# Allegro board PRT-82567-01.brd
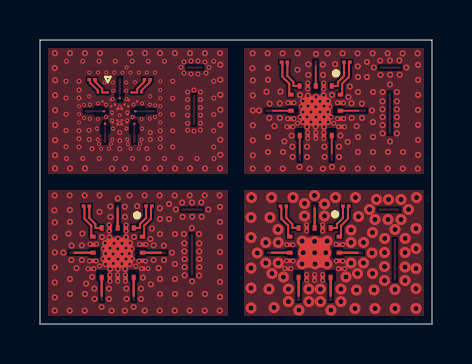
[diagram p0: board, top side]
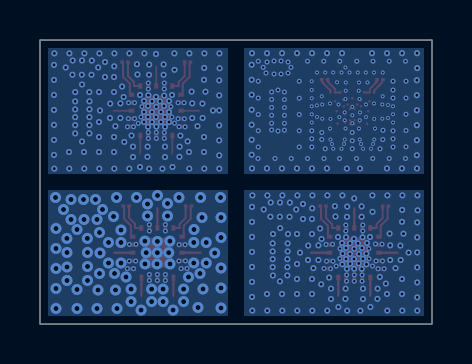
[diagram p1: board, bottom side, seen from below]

Outline 19.6 x 14.2 mm; copper layers: TOP, LAYER_2, LAYER_3, BOTTOM. Coordinates in mm from the lower left corner of the outline.
Outline path: 0,14.2 0,0 19.6,0 19.6,14.2 0,14.2

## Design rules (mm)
constraint set DEFAULT: min track width 0.1
nets with their own width: min track width 0.075; nets RF1_4 RF2_4 RF3_4 RF4_4 RFC_4

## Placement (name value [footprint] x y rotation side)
NOREF  -  []  9.8 14.51 0 top
NOREF#2  -  []  19.6 0 90 top
NOREF#3  -  []  59.4 56.6 0 top
NOREF#4  -  []  -14.29 -36.18 0 top
NOREF#5  -  []  0 0 0 top
NOREF#6  -  []  -35.6 51.6 0 top
NOREF#7  -  []  -27.01 -52.55 0 top
NOREF#8  -  []  -200.87 86.32 0 top
NOREF#9  -  []  70.93 -66.91 0 top
NOREF#10  -  []  -0.19 7.09 0 top
U1  -  [IC_LGA_3P0X3P0_21P]  3.88 3.56 270 top
U2  -  [IC_LGA_3P0X3P0_21P]  13.73 3.56 270 top
U3  -  [IC_DIE_2440X2094_33]  3.98 10.66 0 top
U4  -  [IC_LGA_3P0X3P0_21P]  13.78 10.66 270 top

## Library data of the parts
U1 U2 U4 = IC_SHAGGY_LGA_21P
U3 = IC_SHAGGY_DIE_33P

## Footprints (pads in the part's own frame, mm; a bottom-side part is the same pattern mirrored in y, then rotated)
IC_DIE_2440X2094_33
  round 0.127 smd: 1(1.091,0.913) 2(0.592,0.913) 3(-0.592,0.913) 4(-1.091,0.913) 5(-1.129,-0.959) 6(-0.303,-0.94) 7(0.303,-0.94) 8(1.129,-0.959) 9(1.091,-0.412) 10(0.859,0.47) 11(0.785,-0.027) 12(0.732,-0.648) 13(0.428,0.216) 14(0.446,0.531) 15(0.353,-0.585) 16(0.379,-0.181) 17(0.239,0.306) 18(0.114,-0.68) 19(0.114,-0.48) 20(0.114,0.091) 21(0,0.629) 22(-0.114,-0.68) 23(-0.114,-0.48) 24(-0.114,0.091) 25(-0.239,0.306) 26(-0.353,-0.585) 27(-0.379,-0.181) 28(-0.428,0.216) 29(-0.446,0.531) 30(-0.732,-0.648) 31(-0.785,-0.027) 32(-0.859,0.47) 33(-1.091,-0.412)
IC_LGA_3P0X3P0_21P
  rect 0.275x0.2 smd: 1(-1.238,0.8) 2(-1.238,0.4) 3(-1.238,0) 4(-1.238,-0.4) 5(-1.238,-0.8) 11(1.238,-0.8) 12(1.238,-0.4) 13(1.238,0) 14(1.238,0.4) 15(1.238,0.8)
  rect 0.2x0.275 smd: 6(-0.8,-1.238) 7(-0.4,-1.238) 8(0,-1.238) 9(0.4,-1.238) 10(0.8,-1.238) 16(0.8,1.238) 17(0.4,1.238) 18(0,1.238) 19(-0.4,1.238) 20(-0.8,1.238)
  rrect 1.5x1.5 smd: 21(0,0)

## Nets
GND_1: U1.2 U1.4 U1.7 U1.9 U1.10 U1.12 U1.13 U1.14 U1.16 U1.17 U1.19 U1.21
GND_2: U2.2 U2.4 U2.7 U2.9 U2.10 U2.12 U2.13 U2.14 U2.16 U2.17 U2.19 U2.21
GND_3: U3.5 U3.6 U3.7 U3.8 U3.9 U3.10 U3.13 U3.14 U3.15 U3.16 U3.17 U3.18 U3.19 U3.20 U3.22 U3.23 U3.24 U3.25 U3.26 U3.27 U3.28 U3.29 U3.32 U3.33
GND_4: U4.2 U4.4 U4.7 U4.9 U4.10 U4.12 U4.13 U4.14 U4.16 U4.17 U4.19 U4.21
V1_1: U1.1
V1_2: U2.1
V1_3: U3.2
V1_4: U4.1
V2_1: U1.20
V2_2: U2.20
V2_3: U3.1
V2_4: U4.20
VDD_1: U1.6
VDD_2: U2.6
VDD_3: U3.4
VDD_4: U4.6
VSS_1: U1.5(VSS_EXT)
VSS_2: U2.5(VSS_EXT)
VSS_3: U3.3(VSS_EXT)
VSS_4: U4.5(VSS_EXT)
RF1_1: U1.18
RF1_2: U2.18
RF1_3: U3.11
RF1_4: U4.18
RF2_1: U1.15
RF2_2: U2.15
RF2_3: U3.12
RF2_4: U4.15
RF3_1: U1.11
RF3_2: U2.11
RF3_3: U3.30
RF3_4: U4.11
RF4_1: U1.8
RF4_2: U2.8
RF4_3: U3.31
RF4_4: U4.8
RFC_1: U1.3
RFC_2: U2.3
RFC_3: U3.21
RFC_4: U4.3

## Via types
v1: diameter 0.304, hole 0.152, TOP to BOTTOM, 316 vias
v2: diameter 0.25, hole 0.127, TOP to BOTTOM, 153 vias
v3: diameter 0.2, hole 0.102, TOP to BOTTOM, 68 vias
v4: diameter 0.55, hole 0.25, TOP to BOTTOM, 85 vias

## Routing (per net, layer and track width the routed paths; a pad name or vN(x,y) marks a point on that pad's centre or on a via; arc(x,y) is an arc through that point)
GND_1: length 0.9
  TOP w0.1: v2(4.97,3.98) 5.1,3.98 U1.19 ; v2(3.46,4.95) 3.46,4.83 U1.4 3.46,4.78 v2(3.46,4.65) ; v2(4.95,3.14) 5.1,3.14 U1.17 ; U1.16 v2(5.08,2.76) ; U1.9 2.66,3.15 v2(2.8,3.15)
  vias: v1(0.73,6.43) v1(0.72,5.68) v1(0.74,5.08) v1(0.74,4.33) v1(0.74,3.58) v1(0.74,2.83) v1(0.74,2.08) v1(0.74,1.33) v1(0.73,0.67) v1(1.17,3.57) v1(1.43,4.51) v1(1.48,6.43) v1(1.49,5.71) v1(1.5,5.11) v1(1.5,2.25) v1(1.5,1.5) v1(1.49,0.67) v1(1.58,3.92) v1(1.57,3.2) v1(1.82,2.79) v1(2.12,4.52) v1(2.09,3.93) v1(2.09,3.2) v1(2.23,6.43) v1(2.25,1.5) v1(2.23,0.67) v1(2.31,2.02) v1(2.61,2.35) v1(2.72,1.77) v1(2.73,1.26) v1(2.98,6.43) v1(2.98,5.61) v1(3.1,4.35) v1(3.08,0.85) v1(3.25,4.05) v1(3.28,3.52) v1(3.28,2.98) v1(3.45,1.77) v1(3.45,1.25) v1(3.52,5.88) v1(3.52,5.36) v1(3.47,4.33) v1(3.5,3.8) v1(3.45,3.26) v1(3.51,2.76) v1(3.65,3.5) v1(3.58,0.67) v1(3.7,4.03) v1(3.67,3.03) v1(3.89,6.28) v1(3.9,4.26) v1(3.88,3.76) v1(3.9,3.25) v1(3.89,2.76) v1(4.1,4.03) v1(4.1,3.5) v1(4.09,3.02) v1(4.24,5.87) v1(4.25,5.36) v1(4.24,0.67) v1(4.3,4.34) v1(4.3,3.8) v1(4.3,3.25) v1(4.26,2.76) v1(4.32,1.77) v1(4.33,1.26) v1(4.48,6.43) v1(4.5,4.05) v1(4.46,3.52) v1(4.49,2.98) v1(4.7,4.35) v1(4.68,0.85) v1(4.83,5.38) v1(4.86,5.89) v1(5.05,1.77) v1(5.05,1.25) v1(5.14,2.32) v1(5.23,6.43) v1(5.24,0.67) v1(5.52,4.25) v1(5.54,1.98) v1(5.59,4.78) v1(5.68,3.93) v1(5.68,3.2) v1(5.93,2.79) v1(5.98,6.43) v1(5.99,5.79) v1(6,5.25) v1(6,4.5) v1(6,2.25) v1(6,1.5) v1(5.99,0.67) v1(6.19,3.92) v1(6.2,3.2) v1(6.45,6) v1(6.45,5.25) v1(6.6,3.57) v1(6.73,6.43) v1(6.74,0.67) v1(6.79,5.72) v1(6.75,4.5) v1(6.75,3) v1(6.75,2.25) v1(6.75,1.5) v1(7.11,6.07) v1(7.12,5.36) v1(7.2,4.5) v1(7.22,4.03) v1(7.22,3.63) v1(7.23,3.24) v1(7.23,2.84) v1(7.23,2.43) v1(7.48,6.43) v1(7.5,1.5) v1(7.49,0.67) v1(7.6,6.08) v1(7.61,5.37) v1(7.59,4.79) v1(7.6,2.13) v1(7.95,4.5) v1(7.97,4.03) v1(7.97,3.63) v1(7.97,3.24) v1(7.97,2.84) v1(7.96,2.42) v1(8.06,6.08) v1(8.08,5.37) v1(8.23,6.43) v1(8.25,1.5) v1(8.23,0.67) v1(8.41,5.72) v1(8.98,6.43) v1(9,5.86) v1(9,5.11) v1(9,4.36) v1(9,3.6) v1(9,2.85) v1(9,2.1) v1(9,1.35) v1(8.98,0.67) v2(2.39,2.76) v2(2.5,3.99) v2(2.48,3.15) v2(2.7,2.76) v2(2.83,4) v2(2.98,2.9) v2(3.16,3.77) v2(3.15,3.27) v2(3.49,2.46) v2(3.5,2.14) v2(3.88,2.46) v2(3.89,2.14) v2(4.31,4.95) v2(4.31,4.65) v2(4.27,2.46) v2(4.27,2.14) v2(4.6,3.77) v2(4.61,3.27) v2(4.79,2.89) v2(5.3,3.98) v2(5.27,3.14) v2(5.4,2.77)
GND_2: length 0
  TOP w0.1: U2.16 v2(14.92,2.76)
  vias: v2(12.24,2.77) v2(12.34,3.96) v2(12.33,3.16) v2(12.54,2.77) v2(12.64,3.96) v2(12.66,3.15) v2(13.33,4.97) v2(13.33,4.65) v2(13.33,2.48) v2(13.33,2.18) v2(13.73,2.48) v2(13.73,2.18) v2(14.13,4.97) v2(14.13,4.65) v2(14.13,2.48) v2(14.13,2.18) v2(14.8,3.98) v2(14.81,3.15) v2(15.13,3.98) v2(15.14,3.14) v2(15.23,2.77) v4(10.57,6.33) v4(10.55,5.33) v4(10.55,4.33) v4(10.55,2.8) v4(10.55,1.8) v4(10.55,0.8) v4(10.86,3.55) v4(11.29,4.08) v4(11.29,3.05) v4(11.45,1.75) v4(11.5,5.33) v4(11.57,6.33) v4(11.6,2.52) v4(11.7,0.82) v4(11.9,4.72) v4(11.91,4.08) v4(11.91,3.05) v4(12.18,2.35) v4(12.42,1.75) v4(12.42,1.12) v4(12.65,6.33) v4(12.95,0.7) v4(13.11,4.14) v4(13.1,3) v4(13.22,6.03) v4(13.22,5.4) v4(13.16,3.57) v4(13.45,1.75) v4(13.45,1.12) v4(13.72,6.42) v4(13.73,4.13) v4(13.73,3.56) v4(13.75,3) v4(14.02,1.75) v4(14.02,1.12) v4(14.22,6) v4(14.22,5.4) v4(14.29,3.57) v4(14.35,3) v4(14.36,4.14) v4(14.55,0.7) v4(14.78,6.33) v4(15.05,1.75) v4(15.05,1.12) v4(15.3,2.35) v4(15.55,4.7) v4(15.55,4.08) v4(15.55,3.05) v4(15.78,6.33) v4(15.82,1.7) v4(15.75,0.78) v4(15.93,5.38) v4(15.88,2.52) v4(16.18,4.08) v4(16.18,3.05) v4(16.48,5.72) v4(16.62,4.58) v4(16.6,3.55) v4(16.62,2.52) v4(16.7,1.7) v4(16.82,6.22) v4(16.75,5.22) v4(16.75,0.78) v4(17.23,4.28) v4(17.23,3.58) v4(17.23,2.88) v4(17.23,2.17) v4(17.43,6.22) v4(17.4,5.22) v4(17.75,4.72) v4(17.75,1.73) v4(17.75,0.78) v4(18.05,6.22) v4(18.05,5.22) v4(18.25,3.58) v4(18.25,2.85) v4(18.25,2.17) v4(18.26,4.28) v4(18.43,5.72) v4(18.82,6.33) v4(18.8,4.78) v4(18.8,3.77) v4(18.8,2.77) v4(18.8,1.77) v4(18.8,0.78)
GND_3:
  vias: v1(0.75,13.54) v1(0.74,12.79) v1(0.76,12.19) v1(0.76,11.44) v1(0.76,10.69) v1(0.76,9.94) v1(0.76,9.19) v1(0.76,8.44) v1(0.75,7.78) v1(1.5,13.54) v1(1.5,7.78) v1(2.25,13.54) v1(2.25,7.78) v1(3,13.54) v1(3.6,7.77) v1(4.26,7.77) v1(4.5,13.54) v1(5.25,13.54) v1(5.25,7.78) v1(6,13.54) v1(6,7.78) v1(6.75,13.54) v1(6.75,7.78) v1(7.5,13.54) v1(7.5,7.78) v1(8.25,13.54) v1(8.25,7.78) v1(9,13.54) v1(9.02,12.96) v1(9.02,12.21) v1(9.02,11.46) v1(9.02,10.71) v1(9.02,9.96) v1(9.02,9.21) v1(9.02,8.46) v1(9,7.78) v2(1.32,13.14) v2(1.3,12.14) v2(1.3,11.3) v2(1.3,10.49) v2(1.3,9.68) v2(1.3,8.86) v2(1.32,8.28) v2(1.95,12.14) v2(1.95,11.7) v2(1.95,11.3) v2(1.95,9.66) v2(1.95,9.26) v2(1.95,8.85) v2(2.14,13.14) v2(2.14,8.28) v2(2.45,9.69) v2(2.46,9.22) v2(2.6,8.76) v2(2.95,13.14) v2(2.96,8.28) v2(3.76,13.14) v2(3.77,8.28) v2(3.99,9.57) v2(3.99,9.16) v2(3.99,8.76) v2(4.61,13.14) v2(4.62,8.28) v2(5.34,8.76) v2(5.41,13.14) v2(5.4,8.28) v2(5.51,9.57) v2(5.51,9.22) v2(6.01,9.66) v2(6.01,9.26) v2(6.01,8.85) v2(6.22,13.14) v2(6.22,8.28) v2(6.64,12.14) v2(6.64,11.29) v2(6.64,10.47) v2(6.64,9.66) v2(6.64,8.85) v2(7.04,8.28) v2(7.05,12.83) v2(7.2,13.1) v2(7.2,12.55) v2(7.38,11.6) v2(7.38,11.22) v2(7.38,10.82) v2(7.38,10.43) v2(7.38,10.03) v2(7.38,9.69) v2(7.55,13.15) v2(7.55,12.5) v2(7.7,11.7) v2(7.7,9.65) v2(7.85,8.28) v2(7.9,13.15) v2(7.9,12.5) v2(8.02,11.6) v2(8.02,11.23) v2(8.02,10.83) v2(8.02,10.44) v2(8.02,10.04) v2(8.02,9.7) v2(8.25,13.1) v2(8.3,12.55) v2(8.44,12.83) v2(8.69,13.14) v2(8.69,12.14) v2(8.69,11.3) v2(8.69,10.47) v2(8.69,9.66) v2(8.69,8.85) v2(8.7,8.28) v3(1.95,10.89) v3(1.95,10.49) v3(1.95,10.07) v3(2.2,10.95) v3(2.2,10.3) v3(2.46,12.57) v3(2.46,11.39) v3(2.49,10.97) v3(2.49,10.26) v3(2.9,12.57) v3(2.9,11.03) v3(2.89,10.25) v3(2.85,9.78) v3(2.89,9.22) v3(2.95,9) v3(3.05,8.76) v3(3.23,12.07) v3(3.31,12.57) v3(3.3,10.97) v3(3.3,10.35) v3(3.55,9) v3(3.45,8.76) v3(3.65,12.07) v3(3.62,11.25) v3(3.6,10.58) v3(3.61,10.19) v3(3.65,9.78) v3(3.61,9.22) v3(3.71,12.57) v3(3.66,11.66) v3(3.98,10.86) v3(3.98,10.44) v3(3.99,10.04) v3(4.12,12.57) v3(4.33,12.82) v3(4.31,12.07) v3(4.31,11.66) v3(4.33,11.25) v3(4.33,9.78) v3(4.37,10.58) v3(4.36,10.19) v3(4.36,9.22) v3(4.4,9) v3(4.53,12.57) v3(4.53,8.76) v3(4.63,10.34) v3(4.67,10.97) v3(4.75,12.09) v3(4.94,12.57) v3(4.94,8.76) v3(5,9) v3(5.1,11.03) v3(5.08,10.25) v3(5.1,9.78) v3(5.08,9.22) v3(5.34,12.57) v3(5.51,11.39) v3(5.49,10.97) v3(5.49,10.26) v3(5.75,12.57) v3(5.76,10.93) v3(5.75,10.35) v3(6.01,12.14) v3(6.01,11.7) v3(6.01,11.29) v3(6.01,10.89) v3(6.01,10.49) v3(6.01,10.07)
GND_4: length 0.8
  TOP w0.1: v2(13.38,11.75) U4.4 v2(13.38,12.05) ; U4.17 v2(14.87,10.26) ; 13.4,10.58 13.4,10.58 ; U4.19 v2(14.87,11.06) ; 12.55,10.26 v2(12.7,10.26) ; U4.16 v2(14.93,9.86)
  vias: v1(10.63,13.53) v1(10.62,12.79) v1(10.64,12.18) v1(10.64,11.43) v1(10.64,10.68) v1(10.64,9.93) v1(10.64,9.18) v1(10.64,8.43) v1(10.63,7.77) v1(10.95,10.68) v1(11.32,11.62) v1(11.38,13.53) v1(11.39,12.8) v1(11.4,12.21) v1(11.4,9.35) v1(11.4,8.6) v1(11.38,7.77) v1(11.48,11.02) v1(11.47,10.3) v1(11.72,9.89) v1(12.02,11.62) v1(11.99,11.03) v1(11.99,10.3) v1(12.13,13.53) v1(12.13,7.77) v1(12.22,9.13) v1(12.15,8.6) v1(12.58,9.42) v1(12.62,8.87) v1(12.63,8.36) v1(12.88,13.53) v1(12.88,12.71) v1(13,11.45) v1(12.97,7.85) v1(13.15,11.15) v1(13.15,10.6) v1(13.15,10.1) v1(13.35,10.35) v1(13.35,9.86) v1(13.35,8.87) v1(13.35,8.35) v1(13.42,12.98) v1(13.42,12.46) v1(13.39,11.42) v1(13.4,10.9) v1(13.48,7.76) v1(13.6,11.13) v1(13.55,10.6) v1(13.55,10.1) v1(13.8,13.5) v1(13.8,11.36) v1(13.79,10.86) v1(13.8,10.35) v1(13.78,9.87) v1(14,11.13) v1(14,10.6) v1(14,10.1) v1(14.14,12.97) v1(14.14,7.76) v1(14.15,12.46) v1(14.18,11.44) v1(14.2,10.9) v1(14.2,10.35) v1(14.2,9.86) v1(14.22,8.87) v1(14.23,8.36) v1(14.38,13.53) v1(14.4,11.15) v1(14.4,10.6) v1(14.4,10.1) v1(14.6,11.45) v1(14.6,7.85) v1(14.72,12.47) v1(14.76,12.99) v1(14.95,8.87) v1(14.95,8.35) v1(15.02,9.42) v1(15.13,13.53) v1(15.13,7.77) v1(15.42,11.35) v1(15.38,9.1) v1(15.49,11.88) v1(15.58,11.03) v1(15.58,10.3) v1(15.83,9.89) v1(15.88,13.53) v1(15.89,12.88) v1(15.9,12.35) v1(15.9,11.6) v1(15.9,9.35) v1(15.9,8.6) v1(15.88,7.77) v1(16.09,11.02) v1(16.1,10.3) v1(16.35,13.1) v1(16.35,12.35) v1(16.63,13.53) v1(16.65,11.6) v1(16.6,10.68) v1(16.65,10.1) v1(16.65,9.35) v1(16.65,8.6) v1(16.64,7.77) v1(16.69,12.82) v1(17.01,13.17) v1(17.02,12.46) v1(17.13,11.6) v1(17.13,11.13) v1(17.13,10.73) v1(17.13,10.34) v1(17.13,9.94) v1(17.13,9.53) v1(17.38,13.53) v1(17.4,8.6) v1(17.39,7.77) v1(17.5,13.18) v1(17.51,12.46) v1(17.5,11.97) v1(17.5,9.12) v1(17.84,11.6) v1(17.84,11.13) v1(17.84,10.73) v1(17.84,10.34) v1(17.84,9.94) v1(17.84,9.53) v1(17.96,13.18) v1(17.98,12.46) v1(18.13,13.53) v1(18.15,8.6) v1(18.14,7.77) v1(18.32,12.82) v1(18.88,13.53) v1(18.9,12.96) v1(18.9,12.21) v1(18.9,11.46) v1(18.9,10.71) v1(18.9,9.96) v1(18.9,9.21) v1(18.9,8.46) v1(18.89,7.77) v2(12.35,9.86) v2(12.4,11.06) v2(12.38,10.26) v2(12.65,9.86) v2(12.7,11.06) v2(12.88,10.04) v2(13.01,10.35) v2(13.06,10.87) v2(13.38,9.58) v2(13.38,9.28) v2(13.78,9.58) v2(13.78,9.28) v2(14.18,12.05) v2(14.18,11.75) v2(14.18,9.58) v2(14.18,9.28) v2(14.5,10.87) v2(14.55,10.35) v2(14.69,10.03) v2(15.17,11.06) v2(15.18,10.27) v2(15.23,9.86)
V1_1: length 1.5
  TOP w0.101: U1.1 5,4.8 5,5 5.3,5.3 5.3,5.85
V1_2: length 1.5
  TOP w0.101: 15.15,5.85 15.15,5.3 14.84,5 14.84,4.8 U2.1
V1_3: length 1
  TOP w0.1: U3.2 4.86,11.58 4.86,11.76 5.2,12.1 5.2,12.2
V1_4: length 1.6
  TOP w0.101: 15.2,13.05 15.2,12.4 14.9,12.1 14.9,11.9 U4.1
V2_1: length 1.7
  TOP w0.101: 5.55,5.85 5.55,5.26 5.21,4.92 5.21,4.45 U1.20
V2_2: length 1.7
  TOP w0.101: U2.20 15.05,4.45 15.05,4.92 15.4,5.26 15.4,5.85
V2_3: length 0.8
  TOP w0.1: U3.1 5.08,11.68 5.47,12.07 5.47,12.2
V2_4: length 1.8
  TOP w0.101: U4.20 15.11,11.55 15.11,12.02 15.45,12.36 15.45,13.05
VDD_1: length 1.7
  TOP w0.101: 2.22,5.85 2.22,5.26 2.56,4.92 2.56,4.45 U1.6
VDD_2: length 1.7
  TOP w0.101: 12.07,5.85 12.07,5.26 12.41,4.92 12.41,4.45 U2.6
VDD_3: length 0.8
  TOP w0.1: 2.89,11.58 2.89,11.68 2.5,12.07 2.5,12.2
VDD_4: length 1.8
  TOP w0.101: 12.55,11.46 12.46,11.55 12.46,12.02 12.12,12.36 12.12,13.07
VSS_1: length 1.5
  TOP w0.101: 2.47,5.85 2.47,5.3 2.77,5 2.77,4.8 U1.5
VSS_2: length 1.5
  TOP w0.101: 12.32,5.85 12.32,5.3 12.62,5 12.62,4.8 U2.5
VSS_3: length 1
  TOP w0.1: 3.39,11.58 3.11,11.58 3.11,11.76 2.77,12.09 2.77,12.2
VSS_4: length 1.6
  TOP w0.101: 12.37,13.07 12.37,12.4 12.67,12.1 12.67,11.9 U4.5
RF1_1: length 0.9
  TOP w0.121: U1.18 6.04,3.56
RF1_2: length 0.9
  TOP w0.121: U2.18 15.88,3.56
RF1_4: length 0.9
  TOP w0.076: U4.18 15.94,10.66
RF2_1: length 0.9
  TOP w0.121: U1.15 4.68,1.41
RF2_2: length 0.9
  TOP w0.121: U2.15 14.53,1.41
RF2_4: length 0.9
  TOP w0.076: U4.15 14.58,8.51
RF3_1: length 0.9
  TOP w0.121: U1.11 3.08,1.41
RF3_2: length 0.9
  TOP w0.121: U2.11 12.93,1.41
RF3_4: length 0.9
  TOP w0.076: U4.11 12.98,8.51
RF4_1: length 0.9
  TOP w0.121: U1.8 1.73,3.56
RF4_2: length 0.9
  TOP w0.121: U2.8 11.58,3.56
RF4_4: length 0.9
  TOP w0.076: 12.55,10.66 11.63,10.66
RFC_1: length 1
  TOP w0.121: U1.3 3.88,5.78
RFC_2: length 1
  TOP w0.121: U2.3 13.73,5.78
RFC_4: length 1
  TOP w0.076: U4.3 13.78,12.88

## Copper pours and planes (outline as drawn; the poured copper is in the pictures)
GND_1 on TOP: 0.4,0.4 0.4,6.7 9.4,6.7 9.4,0.4
GND_1 on BOTTOM, LAYER_2, LAYER_3: 0.4,6.7 0.4,0.4 9.4,0.4 9.4,6.7
GND_2 on TOP, BOTTOM, LAYER_2, LAYER_3: 10.2,0.4 10.2,6.7 19.2,6.7 19.2,0.4
GND_3 on TOP: 0.4,7.5 0.4,13.8 9.4,13.8 9.4,7.5
GND_3 on BOTTOM, LAYER_2, LAYER_3: 0.4,13.8 0.4,7.5 9.4,7.5 9.4,13.8
GND_4 on TOP, BOTTOM, LAYER_2, LAYER_3: 10.2,13.8 10.2,7.5 19.2,7.5 19.2,13.8

Small or netless copper shapes (teardrops, artwork), in the pictures only: 51 on TOP

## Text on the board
BOTTOM: LAYER 4 (SECONDARY SIDE) | L4
Board Geometry/Soldermask Bottom: SOLDER MASK (SECONDARY SIDE) | BM
Ref Des/Silkscreen Bottom: SILKSCREEN (SECONDARY SIDE) | BS
Board Geometry/Outline: BOARD OUTLINE (TOP VIEW) | BD
TOP: LAYER 1 (PRIMARY SIDE) | L1
Board Geometry/Soldermask Top: SOLDER MASK (PRIMARY SIDE) | TM
Ref Des/Silkscreen Top: SILKSCREEN (PRIMARY SIDE) | TS
LAYER_2: LAYER 2 (GND PLANE) | L2
LAYER_3: LAYER 3 (GND PLANE) | L3
PASTEMASK_BOTTOM: SOLDER PASTE (SECONDARY SIDE) | BP
PASTEMASK_TOP: SOLDER PASTE (PRIMARY SIDE) | TP
User.6: SOLDER PASTE PARTICAL SIZE" <40 MICROMETERS | SOLDER PASTE TYPE: SAC405 (SAC305 IS ACCEPTABLE) | SOLDER PASTE FLUX" NO-CLEAN FLUX | SOLDER PASTE STENCIL TYPE:LASER CUT | SOLDER PASTE STENCIL THICKNESS: < 3.6 MILS | 12. | 13. | 14. | 15. | 16.
User.7: TO PSEMI A MURATA COMPANY. THE INFORMATION IN | (DOC-111030)
User.8: NOTES: UNLESS OTHERWISE SPECIFIED, ALL DIMENSIONS ARE IN METRIC | TRACE WIDTH/SPACE/VIA: | TRACE WIDTHS/SPACING TO BE WITHIN | MINIMUM TRACE WIDTH: | MINIMUM AIR GAP: | MINIMUM VIA PAD DIAMETER: | MATERIAL: | NUMBER OF ELECTRICAL LAYERS IS | MATERIALS AND OVERALL THICKNESS SEE STACKUP DETAIL. | LOAD BOARD AND PREPREG PER IPC-4101.  COPPER FOIL PER IPC-MF-150. | MATERIAL'S GLASS TRANSITION TEMPERATURE (Tg) SHALL BE A MINIMUM OF | 170  CENTIGRADE. | MATERIAL MUST MEET UL796 WITH A FLAMMABILITY RATING OF 94V-0 | VENDOR UL LOGO AND DATE CODE TO BE SCREENED ON THE BOTTOM SIDE. IF NO BOTTOM | SILKSCREEN PROVIDED VENDOR MAY ADD BOTTOM SILKSCREEN. | TOLERANCES: | 6A. LAYER TO LAYER REGISTRATION WITHIN .076mm. | 6B. ALL HOLES TO BE LOCATED WITHIN .076mm OF ORIGINAL CAD DATA. | 6C. ALL HOLES SURROUNDED BY COPPER SHALL HAVE A MINIMUM ANNULAR RING OF .076mm. | 6D. ALL PLATED THROUGH HOLES TO HAVE A MINIMUM .015mm OF PLATING. | 6E. HOLE DIMENSIONS AND TOLERANCES APPLY AFTER PLATING, SEE DRILL HOLE CHART. | 6F. WARP AND TWIST NOT TO EXCEED .254 MM/MM. | PLATING OPTIONS: USE 7A | 7A. IAg - IMMERSION SILVER 6-20 MICROINCHES MINIMUM PER IPC-4553. | 7B. SELECTIVE HARD GOLD FINISH IN THE DUT AND POGOPAD AREA(S), CLASS 1 50-100 MICROINCHES | 7C. HASL (HOT AIR SOLDER LEVEL) SMT PADS MUST BE FLAT TO A MAX OF .076mm (.003") ABOVE | APPLY LPI (LIQUID PROTO-IMAGEABLE) SOLDERMASK OVER BARE COPPER (SMOBC) PER IPC-SM-840 | CLASS "T" TO BOTH SIDES OF PCB. SOLDERMASK COLOR TO BE: GREEN | GERBER FILES REFLECT A ZERO OVERSIZE. VENDOR MAY OVERSIZE AS NEEDED, MAX THICKNESS | .015mm. IT IS NOT ACCEPTABLE FOR SOLDERMASK WEBBING TO DISAPPEAR BETWEEN FINE PITCH BALL PADS. | APPLY SILKSCREEN LEGEND USING WHITE NON-CONDUCTIVE EPOXY INK. TRIM SILKSCREEN FROM ALL | EXPOSED COPPER. | VENDOR TO REMOVE NON-FUNCTIONAL PADS FROM INTERNAL LAYERS. | VENDOR MAY ONLY ADD THIEVING OUTSIDE THE BOARD OUTLINE TO COMPENSATE FOR LOW COPPER DENSITY. | REMOVE ALL BURRS AND BREAK SHARP EDGES, INSIDE CORNER MAXIMUM RADIUS 381mm. | BARE BOARD ELECTRICAL TEST IS REQUIRED. USE THE SUPPLIED IPC-D-356 NETLIST "PRT-82567-01.IPC". | MATRIX DRAWING: USE 14A | 14A. NO MATRIX DRAWING IS REQUIRED. BOARDS TO BE DELIVERED FULLY ROUTED. | 14B. MATRIX DRAWING PROVIDED, SEE FABRICATION DRAWING SHEET 2 OF 2. | 14C. VENDOR TO GENERATE MATRIX DRAWING. VENDOR GENERATED MATRIX DRAWINGS REQUIRE APPROVAL | PLANARITY:  USE 15A,15B. | 15A. VARIATION OF BUMP PADS IN THE Z AXIS TO BE <=5um. | 15B. ALL VIAS TO BE NON-CONDUCTIVE EPOXY FILLED AND COPPER OVERPLATED AFTER PLATING AND BEFORE FINAL | 15C. ALL OTHER VIAS ARE TO BE PLUGGED AND FILLED WITH SOLDERMASK MATERIAL. | CONTROLLED IMPEDANCE REQUIREMENTS: | VENDOR MAY MODIFY DIELECTRIC THICKNESS BY 25% WITHOUT WRITTEN CONSENT. ANY MODIFICATION | GREATER THAN 25% REQUIRES WRITTEN CONSENT FROM PSEMI. | 16A. NO CONTROLLED IMPEDANCE MEASUREMENTS REQUIRED. | 16B. VENDOR TO PROVIDE TEST COUPON AND IMPEDANCE REPORT. | SHORTS DESIGNED IN BOARD: | NET XXXXXXXXXXXX. | NET XXXXXX TO GND, LAYER 4 | IPC-2221 TEST COUPONS A & B REQUIRED. TEST COUPONS SHALL BE IDENTIFIED AND TRACEABLE TO THE LOT. | TEST COUPONS, DATA, CROSSECTIONS VERIFYING WIDTH AND CERTIFICATES OF CONFORMANCE | SHALL ACCOMPANY ALL SHIPMENTS. MATERIAL VERIFICATION SHALL ALSO BE SENT IN WRITING. | SHIPMENTS WITHOUT THESE CERTIFICATIONS WILL NOT BE ACCEPTED. | EXPOSED COPPER ALONG BOARD EDGE IS ACCEPTABLE, POST PANEL ROUTING PROCESS. | INTERPRET DIMENSIONS AND TOLERANCES PER ANSI Y14.5M. | GERBER FILES CONTAIN BOARD OUTLINE FOR ALIGNMENT PURPOSES, | REMOVE PRIOR TO FABRICATION. | FABRICATE PCB PER IPC-6012, LATEST REVISION, TYPE 3, CLASS 2. | THE DETAILED NOTES AND INSTRUCTIONS ON THIS DRAWING SUPERCEDE IPC REQUIREMENTS. | BARE BOARD ACCEPTANCE PER IPC-A-600, LATEST REVISION. | DEVIATIONS BY FABRICATION FACILITY TO BE REPORTED TO PSEMI. | 0.10 - 0.20 uM OVER ELECTROLESS PALLADIUM OVER 3-6 uM OF PALLADIUM PER IPC-4552. | MICROINCHES THICK (KNOOP HARDNESS 130-200) OVER NICKEL PLATE IN ACCORDANCE WITH | IPC-A-600, LATEST REVISION, SECTION 4.0, CLASS 3 (200-600 MICROINCHES THICK). | FABRICATE IN ACCORDANCE WITH IPC-6018, START WITH 1/4oz. COPPER | SURFACE. HASL FINISH TO BE USED ON TEST OR PROTOTYPE BOARDS ONLY. THIS FINISH DOES | NOT COMPLY WITH RoHS DIRECTIVES. | 0.4572mm TRACES ON LAYER 1 ARE 50 OHMS, TRANSMISSION LINES_X_+/-5%. | .XXmm (.XXX") TRACES ON LAYER Y ARE 50 OHMS, MICROSTRIP, +/- 10%. | .XXmm (.XXX") TRACES ON LAYER Y ARE 100 OHMS, DIFFERENTIAL, +/- 10%. | BY PSEMI. PANELIZED BOARDS TO HAVE SAME ORIENTATION AND SHALL BE | ROUTED AND RETAINED WITH BREAK AWAY TABS. SEE DETAIL B. SUPPORT RAIL WIDTH TO BE | 6.35mm - 12.7mm WITH 1.52mm FIDUCIALS AND 3.175mm | TOOLING HOLES IN 3 CORNERS, PANELIZED SOLDERPASTE GERBER TO BE SUBMITTED TO | PSEMI. | SURFACE FINISH. NON-CONDUCTIVE EPOXY (SAN_EI 900 OR EQUIVALENT) IS RECOMMENDED. | EPOXY SHALL NOT PROTRUDE FROM HOLES. THIS APPLIES TO ALL VIAS THAT ARE EXPOSED ON | BOTH SIDES. A SMOOTH COPLANAR FINISH IS REQUIRED WHEN EXPOSED BY SOLDERMASK. | OUTER LAYERS= | INNER LAYERS= | SIDE. | 0.10mm | 0.076 | NA | 4 | 0.0852mm | 20% OF GERBER DATA. | USE 16A | 10%. | TOP | NO | 4. | 5. | 6. | 7. | 8. | 9. | 10. | 11. | 12. | 13. | 14. | 15. | 16. | 17. | 18. | 1. | 2. | 3. | 19.
User.9: TOLERANCES UNLESS OTHERWISE NOTED | DIMENSIONS IN mm/[Inches] | X.X | X.XX | X.XXX | X.XXXX | ANGLES | = +/- .2.5/[.1] | = +/- .25/[.01] | = +/- .127/[.005] | = +/- .0127/[.0005] | = +/- 1/2 DEG | OF | THIS DOCUMENT CONTAINS INFORMATION PROPRIETARY TO | PSEMI. THE INFORMATION IN THIS DOCUMENT IS NOT TO | BE USED OR DUPLICATED IN ANY MANNER WITHOUT THE | PRIOR APPROVAL OF PSEMI. | MATERIAL | FINISH | DO NOT SCALE DRAWING | CONTRACT NO. | DRAWN | CHECKED | ISSUED | REVISIED BY | ZONE | APPROVALS | REV | DATE | COMPANY | TITLE | SIZE | SCALE: | RoHS COMPLIANCE | RELEASE DATE | REVISIONS | DWG NO. | 9380 Carroll Park Drive | San Diego, CA, 92121 | (858)731-9400 Phone | (858)731-9499 Fax | SHEET: | SH | 10/17/2022 | M. MOREY | R.ALIDIO | 01 | 07/08/21 | 1 | NONE | (Make Like PRT-80235-01) | PCB, | PE42546 Shaggy Probe Board | B | PRT-82567 | D | C | A | 4 | 3 | 2
User.10: TOLERANCES UNLESS OTHERWISE NOTED | DIMENSIONS IN mm/[Inches] | X.X | X.XX | X.XXX | X.XXXX | ANGLES | = +/- .2.5/[.1] | = +/- .25/[.01] | = +/- .127/[.005] | = +/- .0127/[.0005] | = +/- 1/2 DEG | OF | THIS DOCUMENT CONTAINS INFORMATION PROPRIETARY TO | PSEMI. THE INFORMATION IN THIS DOCUMENT IS NOT TO | BE USED OR DUPLICATED IN ANY MANNER WITHOUT THE | PRIOR APPROVAL OF PSEMI. | MATERIAL | FINISH | DO NOT SCALE DRAWING | CONTRACT NO. | DRAWN | CHECKED | ISSUED | REVISIED BY | ZONE | APPROVALS | REV | DATE | COMPANY | TITLE | SIZE | SCALE: | RoHS COMPLIANCE | RELEASE DATE | REVISIONS | DWG NO. | 9380 Carroll Park Drive | San Diego, CA, 92121 | (858)731-9400 Phone | (858)731-9499 Fax | SHEET: | SH | 10/18/2022 | M. MOREY | R.ALIDIO | 01 | ---------- | mm/dd/yy | 1 | NONE | PCA, | PE42546 Shaggy LGA Probe Board | B | PRT-82566 | D | C | A | 4 | 3 | ASSEMBLY PRIMARY SIDE | 2
User.11: THIS DOCUMENT CONTAINS INFORMATION PROPRIETARY TO | PSEMI. THE INFORMATION IN THIS DOCUMENT IS NOT TO | BE USED OR DUPLICATED IN ANY MANNER WITHOUT THE | PRIOR APPROVAL OF PSEMI. | REV | OF | SH | SHEET: | DWG NO. | RoHS COMPLIANCE | RELEASE DATE | SIZE | SCALE: | 2 | NONE | 01 | PRT-77450 | PRT-80235 | B | D | C | A | 1 | 3 | 4
User.27: FIG | FINISHED SIZE | 0.1016 | 0.127 | 0.1524 | 0.25 | ALL UNITS ARE IN MILLIMETERS | TOLERANCE | +0.0/-0.1016 | +0.05/-0.127 | +0.0/-0.15 | +0.075/-0.075 | PLATED | QTY | 68 | 153 | 316 | 85 | 622 | TOTAL HOLES: | TOP to BOTTOM
User.34: U1 | U3 | U4 | U2
